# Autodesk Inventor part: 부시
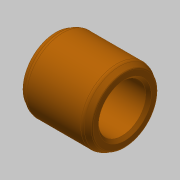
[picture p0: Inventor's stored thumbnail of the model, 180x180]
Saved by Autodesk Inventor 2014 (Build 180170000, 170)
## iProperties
Created: 2018-11
Part Number: 부시
Material: 강철, 연강
Document SubType Name: Modeling
Designer: mduedu
Density: 1 g/cm^3
Appearance: 주황색
Author: mduedu
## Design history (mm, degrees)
sketch "스케치1"
  geometry: C1 r 8.5 at (0, 0); C2 r 13 at (0, 0); 1 further point
  constraints: 2 centre point, 2 coincident
  dimensions: "d0" = 17 diameter of C1; "d1" = 26 diameter of C2
extrude "돌출1" new body sketch "스케치1" distance "d2" = 25; taper "d3" = 0 deg
chamfer "모따기4" distance "d14" = 1; stored, may be unused: second distance "d15" = 2, angle "d16" = 15 deg
chamfer "모따기5" distance "d17" = 2.3; stored, may be unused: second distance "d18" = 2, angle "d19" = 30 deg
chamfer "모따기6" distance "d20" = 2.3; stored, may be unused: second distance "d21" = 2, angle "d22" = 30 deg
fillet "모깎기2" dims "d23" = 2, "d24" = 0.5
fillet "모깎기3" dims "d25" = 2, "d26" = 0.5
node "솔리드1"
